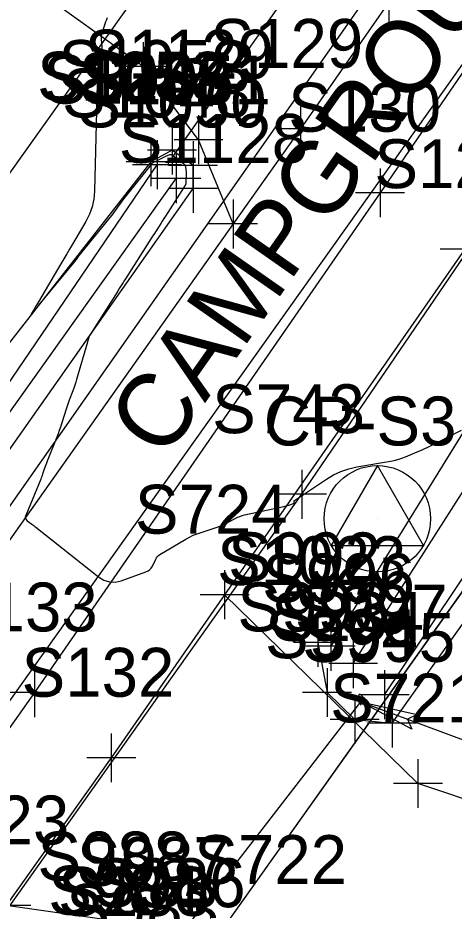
# Model space of a CAD drawing. Extents: x 816928 to 825690, y 436959 to 448212.
# Drawn here: x 819091.2 to 819126.9, y 445330.7 to 445403.7 of the extents above; entities that cross this region are included whole.
import ezdxf

# ---------------------------------------------------------------- set-up
doc = ezdxf.new("R2010")
doc.units = 0
for name, color, linetype in [('SURVEY - CENTERLINE - Preliminary', 7, 'Continuous'), ('SURVEY - CONTOURS - Intermediate with optional Text', 7, 'Continuous'), ('SURVEY - CONTROL with Text', 7, 'Continuous'), ('SURVEY - DRAINAGE - Area Shapes', 7, 'Continuous'), ('SURVEY - DRAINAGE - Pipes and Culverts', 7, 'Continuous'), ('SURVEY - DRAINAGE - Pipes and Culverts - Points - Locators', 7, 'Continuous'), ('SURVEY - DRAINAGE - Pipes and Culverts - Points - Numbers', 7, 'Continuous'), ('SURVEY - DRAINAGE - Pipes and Culverts Text', 7, 'Continuous'), ('SURVEY - DTM - Breaklines', 7, 'Continuous'), ('SURVEY - DTM - Breaklines - Points - Locators', 7, 'Continuous'), ('SURVEY - DTM - Breaklines - Points - Numbers', 7, 'Continuous'), ('SURVEY - PROPERTY - Parcels', 7, 'Continuous'), ('SURVEY - PROPERTY - ROW Lines', 7, 'Continuous'), ('SURVEY - TRANSPORTATION - Features', 7, 'Continuous'), ('SURVEY - TRANSPORTATION - Features - Points - Locators', 7, 'Continuous'), ('SURVEY - TRANSPORTATION - Features - Points - Numbers', 7, 'Continuous'), ('SURVEY - TRANSPORTATION - Roads', 7, 'Continuous'), ('SURVEY - TRANSPORTATION - Roads - Points - Locators', 7, 'Continuous'), ('SURVEY - TRANSPORTATION - Roads - Points - Numbers', 7, 'Continuous'), ('SURVEY - TRANSPORTATION - Roads Text', 7, 'Continuous'), ('SURVEY - UTILITIES - Gas with Text', 7, 'Continuous'), ('SURVEY - UTILITIES - Water - Points - Locators', 7, 'Continuous'), ('SURVEY - UTILITIES - Water - Points - Numbers', 7, 'Continuous'), ('SURVEY - UTILITIES - Water with Text', 7, 'Continuous')]:
    doc.layers.add(name, color=color, linetype=linetype)

msp = doc.modelspace()

# ---------------------------------------------------------------- linework, layer by layer
at = {"layer": 'SURVEY - CENTERLINE - Preliminary'}
msp.add_line((818959.546, 445163.523), (819203.252, 445506.431), dxfattribs=at)
at = {"layer": 'SURVEY - CONTOURS - Intermediate with optional Text'}
for points in [[(819098.523, 445403.738), (819098.458, 445403.565), (819098.396, 445403.391), (819098.336, 445403.216), (819098.28, 445403.04), (819098.099, 445402.464), (819098.066, 445402.34), (819098.045, 445402.215), (819098.036, 445402.088), (819098.039, 445401.959), (819098.078, 445401.362), (819098.081, 445401.234), (819098.074, 445401.108), (819098.057, 445400.982), (819098.028, 445400.858), (819097.823, 445400.095), (819097.784, 445399.931), (819097.755, 445399.765), (819097.736, 445399.598), (819097.727, 445399.43), (819097.494, 445389.543), (819097.438, 445388.892), (819097.302, 445388.264), (819097.086, 445387.658), (819096.79, 445387.076), (819095.691, 445385.211), (819095.456, 445384.811), (819095.22, 445384.412), (819094.985, 445384.012), (819094.749, 445383.613), (819092.913, 445380.495), (819092.835, 445380.363), (819092.757, 445380.231), (819092.679, 445380.099), (819092.601, 445379.967), (819092.347, 445379.536), (819092.308, 445379.465), (819092.3, 445379.439), (819092.322, 445379.456), (819092.375, 445379.516), (819092.85, 445380.09), (819092.86, 445380.102), (819092.869, 445380.113), (819092.879, 445380.125), (819092.888, 445380.138), (819092.917, 445380.177), (819092.924, 445380.186), (819092.93, 445380.194), (819092.937, 445380.203), (819092.943, 445380.211), (819095.899, 445383.816), (819095.96, 445383.891), (819096.02, 445383.967), (819096.079, 445384.044), (819096.136, 445384.122), (819096.323, 445384.377), (819096.363, 445384.431), (819096.404, 445384.485), (819096.446, 445384.538), (819096.488, 445384.591), (819098.892, 445387.555), (819099.009, 445387.702), (819099.125, 445387.851), (819099.238, 445388.001), (819099.349, 445388.153), (819099.708, 445388.652), (819099.785, 445388.758), (819099.864, 445388.863), (819099.945, 445388.968), (819100.026, 445389.071), (819102.16, 445391.734), (819102.171, 445391.749), (819102.183, 445391.764), (819102.194, 445391.779), (819102.205, 445391.794), (819102.241, 445391.845), (819102.25, 445391.856), (819102.259, 445391.865), (819102.269, 445391.873), (819102.281, 445391.879), (819103.197, 445392.345), (819103.258, 445392.375), (819103.319, 445392.404), (819103.381, 445392.432), (819103.444, 445392.458), (819103.649, 445392.544), (819103.692, 445392.556), (819103.734, 445392.557), (819103.774, 445392.546), (819103.813, 445392.524), (819104.772, 445391.817), (819104.83, 445391.766), (819104.874, 445391.706), (819104.905, 445391.639), (819104.923, 445391.563), (819104.959, 445391.304), (819104.966, 445391.248), (819104.971, 445391.193), (819104.973, 445391.137), (819104.973, 445391.081), (819104.952, 445390.151), (819104.951, 445390.132), (819104.946, 445390.114), (819104.94, 445390.096), (819104.93, 445390.079), (819104.896, 445390.025), (819104.889, 445390.014), (819104.881, 445390.002), (819104.874, 445389.991), (819104.866, 445389.979), (819104.838, 445389.935), (819104.832, 445389.925), (819104.825, 445389.916), (819104.819, 445389.906), (819104.813, 445389.897), (819103.295, 445387.509), (819103.164, 445387.301), (819103.031, 445387.095), (819102.898, 445386.888), (819102.765, 445386.682), (819102.329, 445386.008), (819102.236, 445385.863), (819102.143, 445385.719), (819102.051, 445385.574), (819101.959, 445385.429), (819100.027, 445382.38), (819099.963, 445382.28), (819099.899, 445382.18), (819099.835, 445382.08), (819099.771, 445381.98), (819099.561, 445381.655), (819099.516, 445381.585), (819099.472, 445381.515), (819099.427, 445381.445), (819099.383, 445381.375), (819097.103, 445377.766), (819097.078, 445377.723), (819097.056, 445377.678), (819097.038, 445377.631), (819097.023, 445377.583), (819096.975, 445377.396), (819096.969, 445377.375), (819096.963, 445377.354), (819096.956, 445377.333), (819096.949, 445377.312), (819096.925, 445377.245), (819096.92, 445377.231), (819096.915, 445377.217), (819096.911, 445377.202), (819096.906, 445377.187), (819096.028, 445374.149), (819095.956, 445373.91), (819095.88, 445373.674), (819095.799, 445373.438), (819095.713, 445373.205), (819095.425, 445372.444), (819095.364, 445372.281), (819095.306, 445372.117), (819095.25, 445371.952), (819095.197, 445371.786), (819094.793, 445370.5), (819094.704, 445370.225), (819094.609, 445369.952), (819094.51, 445369.681), (819094.406, 445369.412), (819093.622, 445367.446), (819093.566, 445367.304), (819093.513, 445367.16), (819093.461, 445367.016), (819093.411, 445366.871), (819093.251, 445366.397), (819093.216, 445366.296), (819093.179, 445366.195), (819093.141, 445366.095), (819093.1, 445365.995), (819091.864, 445363.023), (819091.829, 445362.894), (819091.839, 445362.778), (819091.892, 445362.675), (819091.989, 445362.584), (819092.377, 445362.307), (819092.46, 445362.247), (819092.542, 445362.186), (819092.623, 445362.124), (819092.703, 445362.061), (819097.82, 445357.986), (819098.253, 445357.715), (819098.707, 445357.573), (819099.184, 445357.56), (819099.681, 445357.677), (819101.693, 445358.397), (819101.861, 445358.475), (819102.005, 445358.58), (819102.124, 445358.712), (819102.219, 445358.871), (819102.49, 445359.434), (819102.556, 445359.548), (819102.635, 445359.65), (819102.729, 445359.738), (819102.836, 445359.813), (819104.942, 445361.075), (819105.242, 445361.243), (819105.551, 445361.392), (819105.868, 445361.523), (819106.194, 445361.634), (819107.272, 445361.968), (819107.501, 445362.044), (819107.726, 445362.131), (819107.946, 445362.229), (819108.162, 445362.337), (819108.997, 445362.778), (819109.179, 445362.867), (819109.365, 445362.942), (819109.556, 445363.004), (819109.751, 445363.053), (819112.965, 445363.748), (819113.065, 445363.771), (819113.165, 445363.798), (819113.264, 445363.827), (819113.362, 445363.86), (819113.764, 445364.002), (819113.787, 445364.014), (819113.802, 445364.031), (819113.81, 445364.052), (819113.81, 445364.078), (819113.798, 445364.171), (819113.797, 445364.189), (819113.802, 445364.206), (819113.811, 445364.22), (819113.826, 445364.233), (819116.454, 445365.994), (819117.03, 445366.339), (819117.633, 445366.618), (819118.261, 445366.832), (819118.916, 445366.98), (819121.668, 445367.455), (819121.983, 445367.518), (819122.292, 445367.599), (819122.597, 445367.696), (819122.897, 445367.81), (819123.869, 445368.212), (819124.076, 445368.3), (819124.281, 445368.391), (819124.485, 445368.487), (819124.687, 445368.586), (819127.492, 445369.997)], [(819119.663, 445347.96), (819119.255, 445348.333), (819119.19, 445348.379), (819119.14, 445348.384), (819119.105, 445348.348), (819119.086, 445348.271), (819119.039, 445347.893), (819119.038, 445347.856), (819119.045, 445347.822), (819119.06, 445347.79), (819119.083, 445347.762), (819119.172, 445347.673), (819119.192, 445347.655), (819119.213, 445347.64), (819119.237, 445347.629), (819119.262, 445347.621), (819119.475, 445347.565), (819119.517, 445347.56), (819119.553, 445347.569), (819119.582, 445347.591), (819119.605, 445347.627), (819119.692, 445347.818), (819119.705, 445347.858), (819119.704, 445347.895), (819119.69, 445347.929), (819119.663, 445347.96)]]:
    msp.add_lwpolyline(points, dxfattribs=at)
at = {"layer": 'SURVEY - CONTROL with Text'}
for p, q in [((819120.607, 445367.094), (819116.839, 445360.569)), ((819124.374, 445360.569), (819120.607, 445367.094)), ((819120.607, 445362.744), (819120.607, 445362.744)), ((819116.839, 445360.569), (819124.374, 445360.569))]:
    msp.add_line(p, q, dxfattribs=at)
msp.add_circle((819120.607, 445362.744), 4.35, dxfattribs=at)
at = {"layer": 'SURVEY - DRAINAGE - Area Shapes'}
msp.add_line((818959.546, 445163.523), (819203.252, 445506.431), dxfattribs=at)
at = {"layer": 'SURVEY - DRAINAGE - Pipes and Culverts'}
for p, q in [((819115.333, 445408.652), (819103.536, 445391.898)), ((819101.851, 445325.255), (819119.251, 445347.754))]:
    msp.add_line(p, q, dxfattribs=at)
at = {"layer": 'SURVEY - DRAINAGE - Pipes and Culverts - Points - Locators'}
for p, q in [((819103.536, 445391.648), (819103.536, 445392.148)), ((819103.786, 445391.898), (819103.286, 445391.898)), ((819103.536, 445391.898), (819103.536, 445391.898)), ((819103.536, 445391.898), (819103.536, 445391.898)), ((819119.501, 445347.754), (819119.001, 445347.754)), ((819119.251, 445347.504), (819119.251, 445348.004)), ((819119.251, 445347.754), (819119.251, 445347.754)), ((819119.251, 445347.754), (819119.251, 445347.754))]:
    msp.add_line(p, q, dxfattribs=at)
at = {"layer": 'SURVEY - DRAINAGE - Pipes and Culverts Text'}
msp.add_line((819119.251, 445347.754), (819152.265, 445335.548), dxfattribs=at)
msp.add_lwpolyline([(819119.251, 445347.754), (819123.866, 445346.74), (819123.075, 445346.34), (819123.415, 445345.521)], close=True, dxfattribs=at)
msp.add_lwpolyline([(819119.251, 445347.754), (819123.866, 445346.74), (819123.075, 445346.34), (819123.415, 445345.521), (819119.251, 445347.754)], dxfattribs=at)
at = {"layer": 'SURVEY - DTM - Breaklines'}
for points in [[(819380.404, 445755.141), (819355.578, 445711.888), (819328.616, 445669.931), (819299.268, 445629.736), (819268.215, 445590.476), (819237.204, 445551.148), (819207.272, 445511.316), (819178.097, 445471.355), (819148.961, 445430.516), (819120.831, 445389.41), (819092.595, 445348.525), (819063.764, 445307.701), (819034.576, 445266.965), (819005.716, 445226.512), (818977.706, 445187.397)], [(819115.743, 445352.623), (819116.501, 445348.532), (819118.762, 445346.334), (819121.805, 445346.034), (819151.273, 445387.488), (819170.031, 445419.1), (819198.511, 445465.669), (819205.76, 445465.616), (819229.822, 445502.933), (819247.854, 445531.915), (819280.031, 445574.26), (819278.221, 445576.151), (819274.311, 445579.267), (819242.916, 445541.289), (819216.533, 445504.811), (819186.916, 445462.104), (819160.05, 445422.329), (819116.797, 445352.316)], [(819118.629, 445350.898), (819165.289, 445424.101), (819196.182, 445467.268), (819224.41, 445508.114), (819242.999, 445536.052), (819276.537, 445576.778)], [(819121.197, 445348.347), (819148.072, 445388.457), (819146.917, 445389.221), (819167.079, 445422.999), (819197.484, 445466.128), (819224.892, 445507.372), (819245.683, 445533.866), (819277.871, 445575.058)], [(819055.511, 445319.799), (819082.413, 445356.886), (819105.552, 445389.761), (819105.553, 445391.638), (819103.833, 445392.905), (819102.086, 445391.948), (819073.298, 445355.122), (819048.115, 445322.006)], [(818956.561, 445206.805), (818988.908, 445237.973), (818996.006, 445243.104), (819004.505, 445254.331), (819023.094, 445280.216), (819052.334, 445321.974), (819079.91, 445358.328), (819102.597, 445391.707)], [(818957.887, 445205.786), (818990.182, 445236.343), (818997.6, 445242.102), (819006.167, 445253.219), (819054.017, 445320.891), (819080.835, 445357.817), (819104.169, 445390.571)]]:
    msp.add_lwpolyline(points, dxfattribs=at)
at = {"layer": 'SURVEY - DTM - Breaklines - Points - Locators'}
for p, q in [((819103.833, 445394.905), (819103.833, 445390.905)), ((819102.086, 445393.948), (819102.086, 445389.948)), ((819102.597, 445393.707), (819102.597, 445389.707)), ((819105.553, 445393.638), (819105.553, 445389.638)), ((819105.833, 445392.905), (819101.833, 445392.905)), ((819104.169, 445392.571), (819104.169, 445388.571)), ((819104.086, 445391.948), (819100.086, 445391.948)), ((819104.597, 445391.707), (819100.597, 445391.707)), ((819107.553, 445391.638), (819103.553, 445391.638)), ((819105.552, 445391.761), (819105.552, 445387.761)), ((819120.831, 445391.41), (819120.831, 445387.41)), ((819106.169, 445390.571), (819102.169, 445390.571)), ((819107.552, 445389.761), (819103.552, 445389.761)), ((819122.831, 445389.41), (819118.831, 445389.41)), ((819115.743, 445354.623), (819115.743, 445350.623)), ((819116.797, 445354.316), (819116.797, 445350.316)), ((819118.629, 445352.898), (819118.629, 445348.898)), ((819117.743, 445352.623), (819113.743, 445352.623)), ((819118.797, 445352.316), (819114.797, 445352.316)), ((819116.501, 445350.532), (819116.501, 445346.532)), ((819120.629, 445350.898), (819116.629, 445350.898)), ((819092.595, 445350.525), (819092.595, 445346.525)), ((819121.197, 445350.347), (819121.197, 445346.347)), ((819094.595, 445348.525), (819090.595, 445348.525)), ((819118.501, 445348.532), (819114.501, 445348.532)), ((819123.197, 445348.347), (819119.197, 445348.347)), ((819118.762, 445348.334), (819118.762, 445344.334)), ((819121.805, 445348.034), (819121.805, 445344.034)), ((819120.762, 445346.334), (819116.762, 445346.334)), ((819123.805, 445346.034), (819119.805, 445346.034))]:
    msp.add_line(p, q, dxfattribs=at)
at = {"layer": 'SURVEY - PROPERTY - Parcels'}
for p, q in [((818939.168, 445178.006), (819170.276, 445503.188)), ((819097.287, 445314.178), (819168.538, 445414.432))]:
    msp.add_line(p, q, dxfattribs=at)
at = {"layer": 'SURVEY - PROPERTY - ROW Lines'}
for p, q in [((818939.168, 445178.006), (819182.874, 445520.914)), ((818979.924, 445149.041), (819223.629, 445491.949))]:
    msp.add_line(p, q, dxfattribs=at)
at = {"layer": 'SURVEY - TRANSPORTATION - Features'}
for points in [[(819108.813, 445386.861), (819105.989, 445393.75), (819101.472, 445399.742), (819077.697, 445416.799), (819043.671, 445441.885)], [(819222.663, 445313.83), (819207.425, 445314.203), (819192.655, 445317.318), (819148.319, 445332.892), (819123.922, 445341.083), (819108.123, 445356.526)], [(819232.465, 445284.69), (819229.234, 445276.535), (819200.743, 445290.041), (819188.434, 445305.71), (819145.258, 445321.558), (819112.973, 445327.861), (819090.273, 445331.1)]]:
    msp.add_lwpolyline(points, dxfattribs=at)
at = {"layer": 'SURVEY - TRANSPORTATION - Features - Points - Locators'}
for p, q in [((819121.554, 445407.003), (819121.554, 445403.003)), ((819101.472, 445401.742), (819101.472, 445397.742)), ((819103.472, 445399.742), (819099.472, 445399.742)), ((819105.989, 445395.75), (819105.989, 445391.75)), ((819107.989, 445393.75), (819103.989, 445393.75)), ((819108.813, 445388.861), (819108.813, 445384.861)), ((819110.813, 445386.861), (819106.813, 445386.861)), ((819108.123, 445358.526), (819108.123, 445354.526)), ((819110.123, 445356.526), (819106.123, 445356.526)), ((819123.922, 445343.083), (819123.922, 445339.083)), ((819125.922, 445341.083), (819121.922, 445341.083)), ((819092.273, 445331.1), (819088.273, 445331.1))]:
    msp.add_line(p, q, dxfattribs=at)
at = {"layer": 'SURVEY - TRANSPORTATION - Roads'}
for points in [[(819372.417, 445760.729), (819347.536, 445716.465), (819327.358, 445684.931), (819320.732, 445674.576), (819313.086, 445663.907), (819291.72, 445634.092), (819261.573, 445595.794), (819230.52, 445556.026), (819202.59, 445519.473), (819200.025, 445516.115), (819183.78, 445493.817), (819171.491, 445476.948), (819142.501, 445435.003), (819121.554, 445405.003), (819114.313, 445394.631), (819108.813, 445386.861), (819085.629, 445354.103), (819056.538, 445311.65), (819028.029, 445272.038), (818998.985, 445231.035), (818970.783, 445191.785), (818984.089, 445181.723)], [(819389.734, 445754.855), (819362.957, 445707.555), (819358.085, 445699.888), (819346.624, 445681.852), (819335.583, 445664.476), (819305.378, 445623.327), (819290.371, 445604.569), (819280.694, 445592.472), (819274.745, 445585.035), (819271.707, 445581.193), (819243.267, 445545.212), (819213.411, 445505.8), (819184.164, 445465.705), (819155.799, 445425.75), (819127.747, 445384.791), (819108.123, 445356.526), (819098.861, 445343.186), (819090.273, 445331.1), (819070.114, 445302.733), (819042.351, 445263.277), (819039.074, 445258.681), (819026.695, 445241.322), (819012.76, 445221.779), (818984.089, 445181.723)]]:
    msp.add_lwpolyline(points, dxfattribs=at)
at = {"layer": 'SURVEY - TRANSPORTATION - Roads - Points - Locators'}
for p, q in [((819114.313, 445396.631), (819114.313, 445392.631)), ((819116.313, 445394.631), (819112.313, 445394.631)), ((819129.747, 445384.791), (819125.747, 445384.791)), ((819098.861, 445345.186), (819098.861, 445341.186)), ((819100.861, 445343.186), (819096.861, 445343.186))]:
    msp.add_line(p, q, dxfattribs=at)
at = {"layer": 'SURVEY - UTILITIES - Gas with Text'}
msp.add_lwpolyline([(818968.105, 445195.328), (818969.738, 445197.267), (819012.001, 445253.658), (819064.107, 445326.037), (819122.078, 445408.8), (819183.152, 445497.068), (819237.635, 445568.809), (819293.129, 445639.42), (819349.073, 445723.122), (819383.091, 445785.202)], dxfattribs=at)
at = {"layer": 'SURVEY - UTILITIES - Water - Points - Locators'}
for p, q in [((819114.437, 445366.745), (819114.437, 445362.745)), ((819116.437, 445364.745), (819112.437, 445364.745))]:
    msp.add_line(p, q, dxfattribs=at)
at = {"layer": 'SURVEY - UTILITIES - Water with Text'}
msp.add_lwpolyline([(818803.235, 444799.745), (818822.09, 444847.157), (818840.807, 444894.989), (818859.419, 444943.113), (818878.417, 444989.731), (818897.247, 445035.659), (818918.394, 445078.737), (818943.016, 445121.017), (818943.424, 445156.253), (818947.564, 445166.115), (818971.795, 445201.192), (819041.117, 445261.897), (819085.564, 445324.056), (819114.437, 445364.745), (819142.589, 445406.123), (819261.281, 445567.542), (819325.961, 445650.567), (819357.336, 445697.813), (819381.766, 445739.87), (819404.905, 445782.998)], dxfattribs=at)

# ---------------------------------------------------------------- texts
at = {"layer": 'SURVEY - CONTROL with Text'}
msp.add_text('CP-S3', height=4, dxfattribs=at).set_placement((819111.319, 445368.744))
at = {"layer": 'SURVEY - DRAINAGE - Pipes and Culverts - Points - Numbers'}
for s, p in [('S237', (819096.2, 445396.898)), ('S234', (819111.915, 445352.754)), ('S233', (819094.515, 445330.255))]:
    msp.add_text(s, height=4, dxfattribs=at).set_placement(p)
at = {"layer": 'SURVEY - DTM - Breaklines - Points - Numbers'}
for s, p in [('S1052', (819094.545, 445397.905)), ('S1053', (819092.798, 445396.948)), ('S1049', (819093.293, 445396.707)), ('S1051', (819096.422, 445396.638)), ('S1048', (819094.834, 445395.571)), ('S1050', (819096.091, 445394.761)), ('S130', (819113.322, 445394.41)), ('S992', (819108.407, 445357.623)), ('S1023', (819107.509, 445357.316)), ('S996', (819111.183, 445355.898)), ('S133', (819085.259, 445353.525)), ('S993', (819109.165, 445353.532)), ('S997', (819113.861, 445353.347)), ('S994', (819111.426, 445351.334)), ('S995', (819114.469, 445351.034)), ('S988', (819092.824, 445333.149)), ('S987', (819096.05, 445332.706)), ('S986', (819097.343, 445330.966)), ('S984', (819093.708, 445330.355)), ('S983', (819095.179, 445328.881))]:
    msp.add_text(s, height=4, dxfattribs=at).set_placement(p)
at = {"layer": 'SURVEY - TRANSPORTATION - Features - Points - Numbers'}
for s, p in [('S1129', (819096.685, 445398.75)), ('S1128', (819099.478, 445391.861)), ('S724', (819100.787, 445361.526)), ('S721', (819116.743, 445346.083)), ('S723', (819082.937, 445336.1)), ('S722', (819105.637, 445332.861))]:
    msp.add_text(s, height=4, dxfattribs=at).set_placement(p)
at = {"layer": 'SURVEY - TRANSPORTATION - Roads - Points - Numbers'}
for s, p in [('S129', (819106.961, 445399.631)), ('S128', (819120.364, 445389.791)), ('S132', (819091.525, 445348.186))]:
    msp.add_text(s, height=4, dxfattribs=at).set_placement(p)
at = {"layer": 'SURVEY - TRANSPORTATION - Roads Text'}
msp.add_text('CAMPGROUND RD.', height=6, rotation=54.97513, dxfattribs=at).set_placement((819103.183, 445367.435))
at = {"layer": 'SURVEY - UTILITIES - Water - Points - Numbers'}
msp.add_text('S743', height=4, dxfattribs=at).set_placement((819107.101, 445369.745))

doc.saveas('drawing.dxf')
